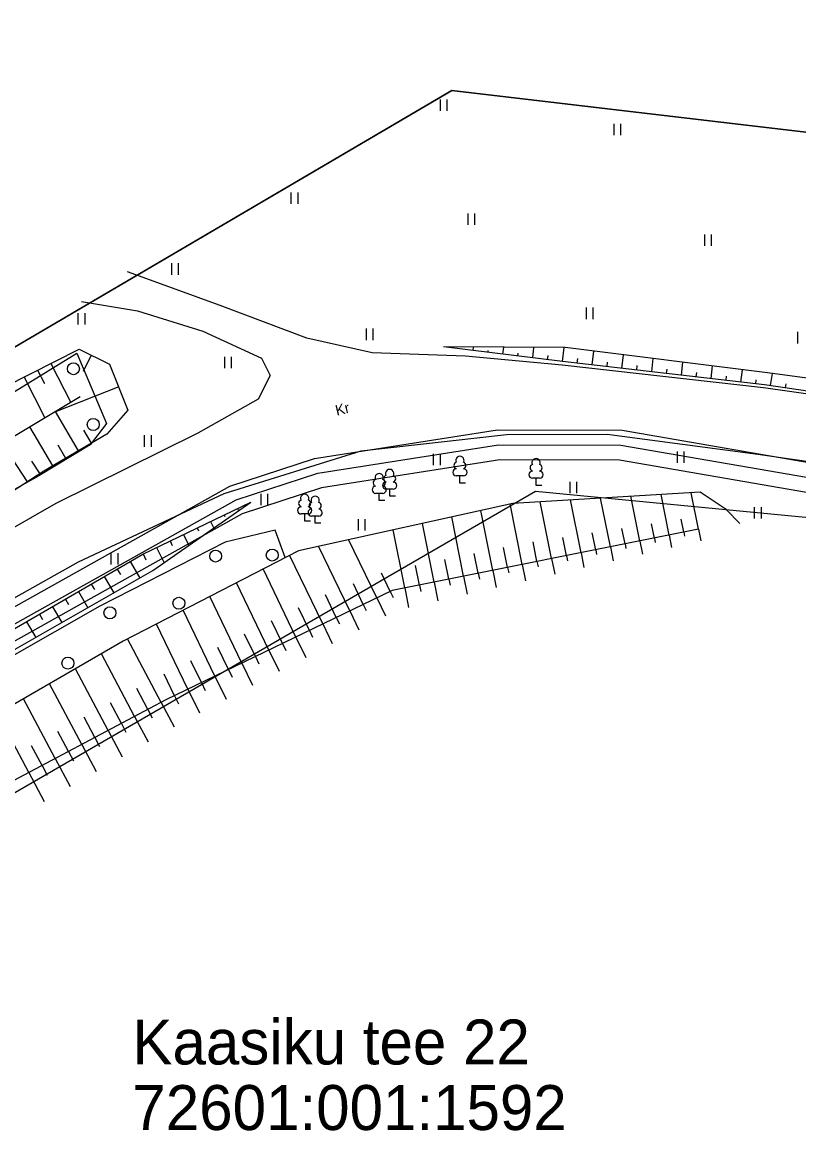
# Model space of a CAD drawing. Extents: x 532656 to 533339, y 6581345 to 6581629.
# Drawn here: x 532824.3 to 532876.2, y 6581458 to 6581531.9 of the extents above; entities that cross this region are included whole.
import ezdxf

# ---------------------------------------------------------------- set-up
doc = ezdxf.new("R2010")
doc.units = 0
for name, color, linetype in [('HALJASTUS', 7, 'Continuous'), ('KASUTUSALA', 7, 'Continuous'), ('PIIR', 7, 'Continuous'), ('PR_SIDE', 7, 'Continuous'), ('PUU', 7, 'Continuous'), ('RELJEEF', 7, 'Continuous'), ('TEE', 7, 'Continuous')]:
    doc.layers.add(name, color=color, linetype=linetype)

msp = doc.modelspace()

# ---------------------------------------------------------------- linework, layer by layer
at = {"layer": 'HALJASTUS'}
for p, q in [((532852.236, 6581526.779), (532852.236, 6581526.018)), ((532852.691, 6581526.779), (532852.691, 6581526.018)), ((532863.831, 6581525.153), (532863.831, 6581524.392)), ((532864.286, 6581525.153), (532864.286, 6581524.392)), ((532842.267, 6581520.571), (532842.267, 6581519.81)), ((532842.722, 6581520.571), (532842.722, 6581519.81)), ((532854.082, 6581519.167), (532854.082, 6581518.406)), ((532854.538, 6581519.167), (532854.538, 6581518.406)), ((532869.886, 6581517.763), (532869.886, 6581517.002)), ((532870.341, 6581517.763), (532870.341, 6581517.002)), ((532834.291, 6581515.842), (532834.291, 6581515.081)), ((532834.746, 6581515.842), (532834.746, 6581515.081)), ((532861.984, 6581512.886), (532861.984, 6581512.125)), ((532862.439, 6581512.886), (532862.439, 6581512.125)), ((532828.045, 6581512.514), (532828.045, 6581511.753)), ((532828.5, 6581512.514), (532828.5, 6581511.753)), ((532847.288, 6581511.482), (532847.288, 6581510.721)), ((532847.743, 6581511.482), (532847.743, 6581510.721)), ((532876.09, 6581511.26), (532876.09, 6581510.499)), ((532837.835, 6581509.601), (532837.835, 6581508.839)), ((532838.29, 6581509.601), (532838.29, 6581508.839)), ((532832.476, 6581504.364), (532832.476, 6581503.603)), ((532832.931, 6581504.364), (532832.931, 6581503.603)), ((532868.061, 6581503.296), (532868.061, 6581502.535)), ((532868.516, 6581503.296), (532868.516, 6581502.535)), ((532851.772, 6581503.127), (532851.772, 6581502.366)), ((532852.227, 6581503.127), (532852.227, 6581502.366)), ((532860.887, 6581501.269), (532860.887, 6581500.508)), ((532861.342, 6581501.269), (532861.342, 6581500.508)), ((532840.252, 6581500.467), (532840.252, 6581499.705)), ((532840.707, 6581500.467), (532840.707, 6581499.705)), ((532873.209, 6581499.58), (532873.209, 6581498.819)), ((532873.665, 6581499.58), (532873.665, 6581498.819)), ((532846.75, 6581498.777), (532846.75, 6581498.016)), ((532847.205, 6581498.777), (532847.205, 6581498.016)), ((532830.25, 6581496.497), (532830.25, 6581495.736)), ((532830.705, 6581496.497), (532830.705, 6581495.736))]:
    msp.add_line(p, q, dxfattribs=at)
for points in [[(532721.1, 6581447.682), (532733.142, 6581454.211), (532742.937, 6581459.756), (532755.429, 6581468.339), (532768.305, 6581476.764), (532777.997, 6581483.673), (532789.089, 6581489.567), (532799.681, 6581496.557), (532811.18, 6581500.395), (532821.912, 6581506.13), (532827.971, 6581509.845), (532829.953, 6581505.15), (532828.861, 6581503.722), (532825.427, 6581501.661), (532814.712, 6581495.648), (532804.124, 6581488.612), (532793.929, 6581483.263), (532783.661, 6581477.253), (532773.13, 6581470.373), (532764.138, 6581465.563), (532755.607, 6581460.651), (532747.092, 6581454.599)], [(532841.895, 6581496.214), (532841.228, 6581498.032), (532837.877, 6581497.24), (532829.506, 6581492.968), (532820.466, 6581487.82), (532815.76, 6581485.797)]]:
    msp.add_lwpolyline(points, dxfattribs=at)
for centre in [(532827.745, 6581508.807), (532829.068, 6581505.086), (532837.245, 6581496.311), (532841.024, 6581496.373), (532834.79, 6581493.159), (532830.186, 6581492.521), (532827.376, 6581489.166)]:
    msp.add_circle(centre, 0.4, dxfattribs=at)
at = {"layer": 'KASUTUSALA'}
for points in [[(532799.662, 6581479.424), (532838.202, 6581500.971), (532843.839, 6581502.808), (532856.06, 6581504.74), (532864.381, 6581504.708), (532878.783, 6581502.228), (532905.462, 6581499.009), (532934.405, 6581494.582), (532940.328, 6581500.726), (532975.953, 6581496.54), (532984.828, 6581495.375), (532991.779, 6581493.915), (533009.862, 6581492.726), (533014.729, 6581492.033), (533013.98, 6581493.304), (533015.896, 6581507.087)], [(533020.132, 6581489.243), (533009.655, 6581490.735), (532991.507, 6581491.928), (532984.492, 6581493.402), (532975.706, 6581494.555), (532941.079, 6581498.624), (532935.126, 6581492.449), (532905.191, 6581497.027), (532878.493, 6581500.248), (532864.206, 6581502.709), (532856.214, 6581502.739), (532844.308, 6581500.857), (532839.008, 6581499.129), (532800.682, 6581477.703)]]:
    msp.add_lwpolyline(points, dxfattribs=at)
at = {"layer": 'PIIR'}
for points in [[(532997.696, 6581510.35), (532853.02, 6581527.38), (532766.54, 6581476.67), (532710.965, 6581584.147)], [(532997.696, 6581484.842), (532936.25, 6581492.16), (532895.36, 6581497.07), (532858.61, 6581500.62), (532765.26, 6581446.64), (532740.99, 6581450.83), (532726.7, 6581453.3), (532853.02, 6581527.38), (532997.696, 6581510.35)]]:
    msp.add_lwpolyline(points, dxfattribs=at)
msp.add_lwpolyline([(532858.61, 6581500.62), (532765.26, 6581446.64), (532882.56, 6581425.55), (532888.42, 6581457.95), (532895.36, 6581497.07)], close=True, dxfattribs=at)
at = {"layer": 'PR_SIDE'}
msp.add_lwpolyline([(532685.797, 6581460.812), (532752.673, 6581449.895), (532752.642, 6581449.863), (532756.241, 6581452.319), (532771.22, 6581460.368), (532800.172, 6581478.564), (532838.605, 6581500.05), (532844.074, 6581501.833), (532856.137, 6581503.74), (532864.294, 6581503.709), (532878.638, 6581501.239), (532905.327, 6581498.018), (532934.766, 6581493.516), (532940.704, 6581499.675), (532975.83, 6581495.548), (532984.66, 6581494.389), (532991.644, 6581492.922), (533009.759, 6581491.731), (533020.322, 6581490.227)], dxfattribs=at)
at = {"layer": 'PUU'}
for p, q in [((532853.793, 6581501.655), (532853.313, 6581501.655)), ((532853.553, 6581501.18), (532853.553, 6581501.655)), ((532853.933, 6581501.18), (532853.553, 6581501.18)), ((532858.879, 6581501.5), (532858.399, 6581501.5)), ((532858.639, 6581501.025), (532858.639, 6581501.5)), ((532859.019, 6581501.025), (532858.639, 6581501.025)), ((532848.405, 6581500.492), (532847.925, 6581500.492)), ((532848.165, 6581500.017), (532848.165, 6581500.492)), ((532849.104, 6581500.771), (532848.624, 6581500.771)), ((532848.864, 6581500.296), (532848.864, 6581500.771)), ((532849.244, 6581500.296), (532848.864, 6581500.296)), ((532848.545, 6581500.017), (532848.165, 6581500.017)), ((532843.43, 6581499.117), (532842.95, 6581499.117)), ((532843.19, 6581498.642), (532843.19, 6581499.117)), ((532844.129, 6581498.973), (532843.649, 6581498.973)), ((532843.889, 6581498.498), (532843.889, 6581498.973)), ((532843.57, 6581498.642), (532843.19, 6581498.642)), ((532844.269, 6581498.498), (532843.889, 6581498.498))]:
    msp.add_line(p, q, dxfattribs=at)
for centre, radius, start, end in [((532853.383, 6581502.353), 0.233, 109.02174, 253.14154), ((532853.553, 6581502.7), 0.277, 332.5799, 207.4201), ((532853.723, 6581502.353), 0.233, 286.85082, 70.98591), ((532858.469, 6581502.198), 0.233, 109.02174, 253.14154), ((532858.639, 6581502.545), 0.277, 332.5799, 207.4201), ((532858.809, 6581502.198), 0.233, 286.85082, 70.98591), ((532848.165, 6581501.537), 0.277, 332.5799, 207.4201), ((532848.694, 6581501.469), 0.233, 109.02174, 253.14154), ((532848.864, 6581501.816), 0.277, 332.5799, 207.4201), ((532849.034, 6581501.469), 0.233, 286.85082, 70.98591), ((532853.316, 6581501.892), 0.238, 90.0016, 269.3953), ((532853.79, 6581501.892), 0.238, 270.6047, 89.9984), ((532858.401, 6581501.738), 0.238, 90.0016, 269.3953), ((532858.876, 6581501.738), 0.238, 270.6047, 89.9984), ((532847.928, 6581500.729), 0.238, 90.0016, 269.3953), ((532847.995, 6581501.189), 0.233, 109.02174, 253.14154), ((532848.627, 6581501.009), 0.238, 90.0016, 269.3953), ((532848.335, 6581501.189), 0.233, 286.85082, 70.98591), ((532848.403, 6581500.729), 0.238, 270.6047, 89.9984), ((532849.101, 6581501.009), 0.238, 270.6047, 89.9984), ((532843.19, 6581500.162), 0.277, 332.5799, 207.4201), ((532843.889, 6581500.018), 0.277, 332.5799, 207.4201), ((532842.953, 6581499.355), 0.238, 90.0016, 269.3953), ((532843.02, 6581499.815), 0.233, 109.02174, 253.14154), ((532843.651, 6581499.21), 0.238, 90.0016, 269.3953), ((532843.36, 6581499.815), 0.233, 286.85082, 70.98591), ((532843.428, 6581499.355), 0.238, 270.6047, 89.9984), ((532843.719, 6581499.671), 0.233, 109.02174, 253.14154), ((532844.059, 6581499.671), 0.233, 286.85082, 70.98591), ((532844.126, 6581499.21), 0.238, 270.6047, 89.9984)]:
    msp.add_arc(centre, radius, start, end, dxfattribs=at)
at = {"layer": 'RELJEEF'}
for p, q in [((532853.45, 6581510.145), (532853.455, 6581510.184)), ((532854.443, 6581510.023), (532854.472, 6581510.256)), ((532855.435, 6581509.9), (532855.45, 6581510.017)), ((532856.428, 6581509.777), (532856.486, 6581510.245)), ((532857.42, 6581509.655), (532857.444, 6581509.85)), ((532858.413, 6581509.532), (532858.499, 6581510.234)), ((532860.398, 6581509.287), (532860.505, 6581510.223)), ((532862.385, 6581509.059), (532862.491, 6581509.984)), ((532826.249, 6581509.157), (532827.565, 6581506.555)), ((532828.932, 6581509.721), (532828.392, 6581508.615)), ((532859.405, 6581509.41), (532859.439, 6581509.682)), ((532861.391, 6581509.173), (532861.427, 6581509.485)), ((532863.378, 6581508.945), (532863.413, 6581509.25)), ((532864.372, 6581508.832), (532864.475, 6581509.735)), ((532866.359, 6581508.604), (532866.46, 6581509.487)), ((532868.346, 6581508.376), (532868.444, 6581509.238)), ((532825.357, 6581508.706), (532825.806, 6581507.817)), ((532865.365, 6581508.718), (532865.399, 6581509.015)), ((532867.352, 6581508.49), (532867.385, 6581508.781)), ((532869.339, 6581508.262), (532869.372, 6581508.546)), ((532870.333, 6581508.148), (532870.429, 6581508.99)), ((532871.326, 6581508.035), (532871.358, 6581508.312)), ((532872.32, 6581507.921), (532872.414, 6581508.742)), ((532874.305, 6581507.68), (532874.424, 6581508.487)), ((532824.465, 6581508.255), (532825.845, 6581505.524)), ((532830.769, 6581507.608), (532826.438, 6581505.88)), ((532873.313, 6581507.807), (532873.344, 6581508.077)), ((532875.294, 6581507.534), (532875.334, 6581507.808)), ((532828.094, 6581503.335), (532826.556, 6581505.95)), ((532826.371, 6581502.321), (532824.84, 6581504.922)), ((532828.956, 6581503.843), (532828.442, 6581504.716)), ((532824.676, 6581501.26), (532823.014, 6581503.828)), ((532827.233, 6581502.828), (532826.721, 6581503.697)), ((532825.516, 6581501.803), (532824.968, 6581502.649)), ((532863.602, 6581496.921), (532862.953, 6581500.175)), ((532865.564, 6581497.312), (532864.968, 6581500.296)), ((532867.525, 6581497.704), (532866.983, 6581500.417)), ((532869.486, 6581498.095), (532868.999, 6581500.538)), ((532838.709, 6581499.483), (532838.778, 6581499.338)), ((532857.719, 6581495.746), (532856.913, 6581499.784)), ((532859.68, 6581496.138), (532858.922, 6581499.932)), ((532861.641, 6581496.529), (532860.938, 6581500.053)), ((532837.807, 6581499.049), (532837.854, 6581498.952)), ((532853.796, 6581494.963), (532853.005, 6581498.923)), ((532855.757, 6581495.355), (532854.959, 6581499.354)), ((532868.506, 6581497.9), (532868.334, 6581498.759)), ((532836.005, 6581498.182), (532836.099, 6581497.987)), ((532836.906, 6581498.616), (532837.117, 6581498.176)), ((532849.873, 6581494.18), (532849.098, 6581498.062)), ((532851.835, 6581494.572), (532851.052, 6581498.492)), ((532864.583, 6581497.116), (532864.376, 6581498.156)), ((532866.544, 6581497.508), (532866.355, 6581498.457)), ((532869.486, 6581498.095), (532869.641, 6581497.32)), ((532834.203, 6581497.316), (532834.344, 6581497.022)), ((532835.104, 6581497.749), (532835.457, 6581497.015)), ((532848.003, 6581493.517), (532846.124, 6581497.406)), ((532858.699, 6581495.942), (532858.438, 6581497.252)), ((532860.661, 6581496.333), (532860.417, 6581497.553)), ((532862.622, 6581496.725), (532862.396, 6581497.855)), ((532865.564, 6581497.312), (532865.739, 6581496.433)), ((532866.544, 6581497.508), (532866.601, 6581497.224)), ((532867.525, 6581497.704), (532867.69, 6581496.876)), ((532868.506, 6581497.9), (532868.559, 6581497.632)), ((532833.301, 6581496.882), (532833.796, 6581495.854)), ((532846.202, 6581492.647), (532844.117, 6581496.964)), ((532854.777, 6581495.159), (532854.512, 6581496.485)), ((532856.738, 6581495.55), (532856.471, 6581496.89)), ((532861.641, 6581496.529), (532861.837, 6581495.546)), ((532862.622, 6581496.725), (532862.686, 6581496.406)), ((532863.602, 6581496.921), (532863.788, 6581495.99)), ((532864.583, 6581497.116), (532864.643, 6581496.815)), ((532831.535, 6581495.948), (532832.181, 6581494.838)), ((532832.4, 6581496.449), (532832.587, 6581496.06)), ((532844.401, 6581491.777), (532842.186, 6581496.364)), ((532852.815, 6581494.767), (532852.553, 6581496.081)), ((532857.719, 6581495.746), (532857.935, 6581494.66)), ((532858.699, 6581495.942), (532858.77, 6581495.588)), ((532859.68, 6581496.138), (532859.886, 6581495.103)), ((532860.661, 6581496.333), (532860.728, 6581495.997)), ((532830.671, 6581495.445), (532830.884, 6581495.078)), ((532842.601, 6581490.907), (532840.408, 6581495.446)), ((532848.904, 6581493.952), (532848.312, 6581495.177)), ((532850.854, 6581494.376), (532850.594, 6581495.676)), ((532854.777, 6581495.159), (532854.854, 6581494.771)), ((532855.757, 6581495.355), (532855.985, 6581494.216)), ((532856.738, 6581495.55), (532856.812, 6581495.18)), ((532828.942, 6581494.438), (532829.153, 6581494.077)), ((532829.806, 6581494.942), (532830.443, 6581493.848)), ((532840.8, 6581490.037), (532838.63, 6581494.528)), ((532847.103, 6581493.082), (532846.442, 6581494.45)), ((532850.854, 6581494.376), (532850.938, 6581493.953)), ((532851.835, 6581494.572), (532852.083, 6581493.33)), ((532852.815, 6581494.767), (532852.896, 6581494.362)), ((532853.796, 6581494.963), (532854.034, 6581493.773)), ((532828.078, 6581493.935), (532828.705, 6581492.858)), ((532838.999, 6581489.167), (532836.852, 6581493.611)), ((532845.302, 6581492.212), (532844.572, 6581493.722)), ((532848.003, 6581493.517), (532848.58, 6581492.322)), ((532848.904, 6581493.952), (532849.099, 6581493.548)), ((532849.873, 6581494.18), (532850.132, 6581492.886)), ((532826.349, 6581492.929), (532826.967, 6581491.868)), ((532827.214, 6581493.432), (532827.421, 6581493.076)), ((532843.501, 6581491.342), (532842.766, 6581492.863)), ((532847.103, 6581493.082), (532847.3, 6581492.674)), ((532825.485, 6581492.426), (532825.69, 6581492.075)), ((532837.198, 6581488.297), (532835.074, 6581492.693)), ((532845.302, 6581492.212), (532845.508, 6581491.785)), ((532846.202, 6581492.647), (532846.807, 6581491.396)), ((532824.621, 6581491.923), (532825.229, 6581490.878)), ((532835.397, 6581487.427), (532833.296, 6581491.775)), ((532841.7, 6581490.472), (532840.973, 6581491.977)), ((532843.501, 6581491.342), (532843.716, 6581490.897)), ((532844.401, 6581491.777), (532845.033, 6581490.47)), ((532833.602, 6581486.545), (532831.361, 6581490.777)), ((532839.899, 6581489.602), (532839.18, 6581491.091)), ((532842.601, 6581490.907), (532843.259, 6581489.544)), ((532838.098, 6581488.732), (532837.387, 6581490.205)), ((532840.8, 6581490.037), (532841.485, 6581488.618)), ((532841.7, 6581490.472), (532841.924, 6581490.008)), ((532831.835, 6581485.609), (532829.621, 6581489.79)), ((532836.298, 6581487.862), (532835.593, 6581489.319)), ((532838.999, 6581489.167), (532839.712, 6581487.691)), ((532839.899, 6581489.602), (532840.132, 6581489.119)), ((532830.067, 6581484.673), (532827.888, 6581488.789)), ((532834.497, 6581486.992), (532833.8, 6581488.434)), ((532838.098, 6581488.732), (532838.341, 6581488.231)), ((532828.3, 6581483.737), (532826.155, 6581487.788)), ((532836.298, 6581487.862), (532836.549, 6581487.342)), ((532837.198, 6581488.297), (532837.938, 6581486.765)), ((532832.718, 6581486.077), (532831.975, 6581487.482)), ((532834.497, 6581486.992), (532834.757, 6581486.453)), ((532835.397, 6581487.427), (532836.164, 6581485.839)), ((532826.532, 6581482.801), (532824.422, 6581486.787)), ((532830.951, 6581485.141), (532830.219, 6581486.524)), ((532833.602, 6581486.545), (532834.463, 6581484.92)), ((532824.765, 6581481.865), (532822.688, 6581485.786)), ((532829.183, 6581484.205), (532828.463, 6581485.566)), ((532831.835, 6581485.609), (532832.729, 6581483.921)), ((532832.718, 6581486.077), (532833.011, 6581485.525)), ((532830.067, 6581484.673), (532830.994, 6581482.923)), ((532830.951, 6581485.141), (532831.254, 6581484.568)), ((532827.416, 6581483.269), (532826.707, 6581484.609)), ((532829.183, 6581484.205), (532829.498, 6581483.611)), ((532825.649, 6581482.333), (532824.951, 6581483.651)), ((532827.416, 6581483.269), (532827.742, 6581482.654)), ((532828.3, 6581483.737), (532829.26, 6581481.924)), ((532826.532, 6581482.801), (532827.526, 6581480.925)), ((532824.765, 6581481.865), (532825.791, 6581479.927)), ((532825.649, 6581482.333), (532825.985, 6581481.698))]:
    msp.add_line(p, q, dxfattribs=at)
for points in [[(532990.32, 6581511.282), (532991.842, 6581500.091), (532992.434, 6581496.294), (532992.243, 6581494.55), (532987.443, 6581493.612), (532974.703, 6581494.609), (532961.03, 6581496.282), (532943.56, 6581498.546), (532930.091, 6581500.627), (532917.608, 6581502.219), (532904.555, 6581504.35), (532889.827, 6581506.424), (532874.089, 6581508.532), (532860.585, 6581510.222), (532852.458, 6581510.268)], [(532991.295, 6581511.036), (532993.491, 6581500.256), (532994.205, 6581496.453), (532994.102, 6581494.569), (532992.018, 6581493.179), (532987.251, 6581492.777), (532974.607, 6581493.731), (532960.859, 6581495.351), (532943.377, 6581497.668), (532929.887, 6581499.542), (532917.361, 6581501.265), (532904.238, 6581503.289), (532889.482, 6581505.445), (532873.903, 6581507.739), (532860.397, 6581509.287), (532852.458, 6581510.268)], [(532721.263, 6581447.097), (532732.92, 6581453.737), (532742.055, 6581459.713), (532755.803, 6581467.377), (532769.218, 6581475.56), (532778.77, 6581481.589), (532790.219, 6581488.226), (532800.366, 6581494.087), (532810.651, 6581500.556), (532821.575, 6581506.794), (532828.134, 6581510.111), (532830.167, 6581509.118), (532831.39, 6581506.051), (532829.967, 6581504.438), (532825.771, 6581501.968), (532815.321, 6581495.209), (532804.525, 6581488.672), (532794.271, 6581483.121), (532783.68, 6581476.504), (532772.937, 6581470.48), (532764.365, 6581465.077), (532757.339, 6581460.687), (532745.444, 6581453.46), (532732.401, 6581446.223)], [(532828.197, 6581506.933), (532813.2, 6581497.948), (532803.475, 6581492.013), (532782.112, 6581479.168), (532771.566, 6581473.2), (532756.345, 6581464.055), (532742.954, 6581456.296), (532728.051, 6581447.21)], [(532872.246, 6581498.47), (532871.331, 6581499.421), (532869.589, 6581500.574), (532857.082, 6581499.821), (532842.776, 6581496.668), (532831.067, 6581490.625), (532821.585, 6581485.149), (532803.655, 6581474.2), (532788.457, 6581467.626), (532771.369, 6581458.536), (532758.947, 6581451.9), (532749.245, 6581445.656), (532747.562, 6581444.346), (532747.354, 6581442.902)], [(532804.311, 6581479.139), (532814.017, 6581485.364), (532823.528, 6581491.287), (532832.372, 6581496.435), (532839.597, 6581499.91)], [(532804.311, 6581479.139), (532814.804, 6581484.419), (532823.852, 6581490.093), (532833.054, 6581495.336), (532839.597, 6581499.91)], [(532869.486, 6581498.095), (532849.026, 6581494.011), (532833.913, 6581486.71), (532824.11, 6581481.518), (532807.265, 6581472.455), (532790.383, 6581465.547), (532774.009, 6581454.556), (532755.51, 6581442.881)]]:
    msp.add_lwpolyline(points, dxfattribs=at)
at = {"layer": 'TEE'}
for points in [[(532992.127, 6581511.166), (532994.877, 6581500.414), (532995.992, 6581497.284), (532996.535, 6581494.967), (532995.038, 6581493.06), (532992.109, 6581492.211), (532987.192, 6581492.522), (532974.603, 6581493.571), (532960.836, 6581495.043), (532943.355, 6581497.307), (532929.83, 6581499.24), (532917.328, 6581501.087), (532904.202, 6581503.175), (532889.432, 6581505.339), (532873.836, 6581507.526), (532860.39, 6581509.056), (532853.923, 6581509.639), (532847.694, 6581509.868), (532843.333, 6581510.842), (532837.551, 6581513.019), (532831.36, 6581515.277)], [(532828.292, 6581513.296), (532832.02, 6581512.679), (532836.397, 6581511.316), (532840.31, 6581509.519), (532840.891, 6581508.347), (532840.082, 6581506.769), (532836.051, 6581504.503), (532826.569, 6581499.82), (532816.225, 6581493.907), (532805.282, 6581487.21), (532795.313, 6581481.353), (532784.256, 6581474.69), (532773.891, 6581468.38), (532765.47, 6581463.073)], [(532767.433, 6581459.775), (532769.763, 6581460.862), (532776.446, 6581464.64), (532786.616, 6581471.204), (532796.99, 6581477.695), (532807.38, 6581484.085), (532818.009, 6581490.276), (532828.082, 6581495.934), (532837.804, 6581500.488), (532846.951, 6581503.331), (532856.666, 6581504.417), (532863.379, 6581504.434), (532873.451, 6581503.101), (532883.953, 6581501.601), (532885.768, 6581500.904), (532886.826, 6581499.461), (532886.304, 6581496.797)]]:
    msp.add_lwpolyline(points, dxfattribs=at)

# ---------------------------------------------------------------- texts
at = {"layer": 'PIIR'}
for s, p in [('Kaasiku tee 22', (532831.685, 6581462.386)), ('72601:001:1592', (532831.685, 6581458.011))]:
    msp.add_text(s, height=3, dxfattribs=at).set_placement(p)
at = {"layer": 'TEE'}
msp.add_text('Kr', height=0.7, rotation=14.09408, dxfattribs=at).set_placement((532845.338, 6581505.668))

doc.saveas('drawing.dxf')
